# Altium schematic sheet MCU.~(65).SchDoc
size A3; SheetNumber: 10; SheetTotal: 12
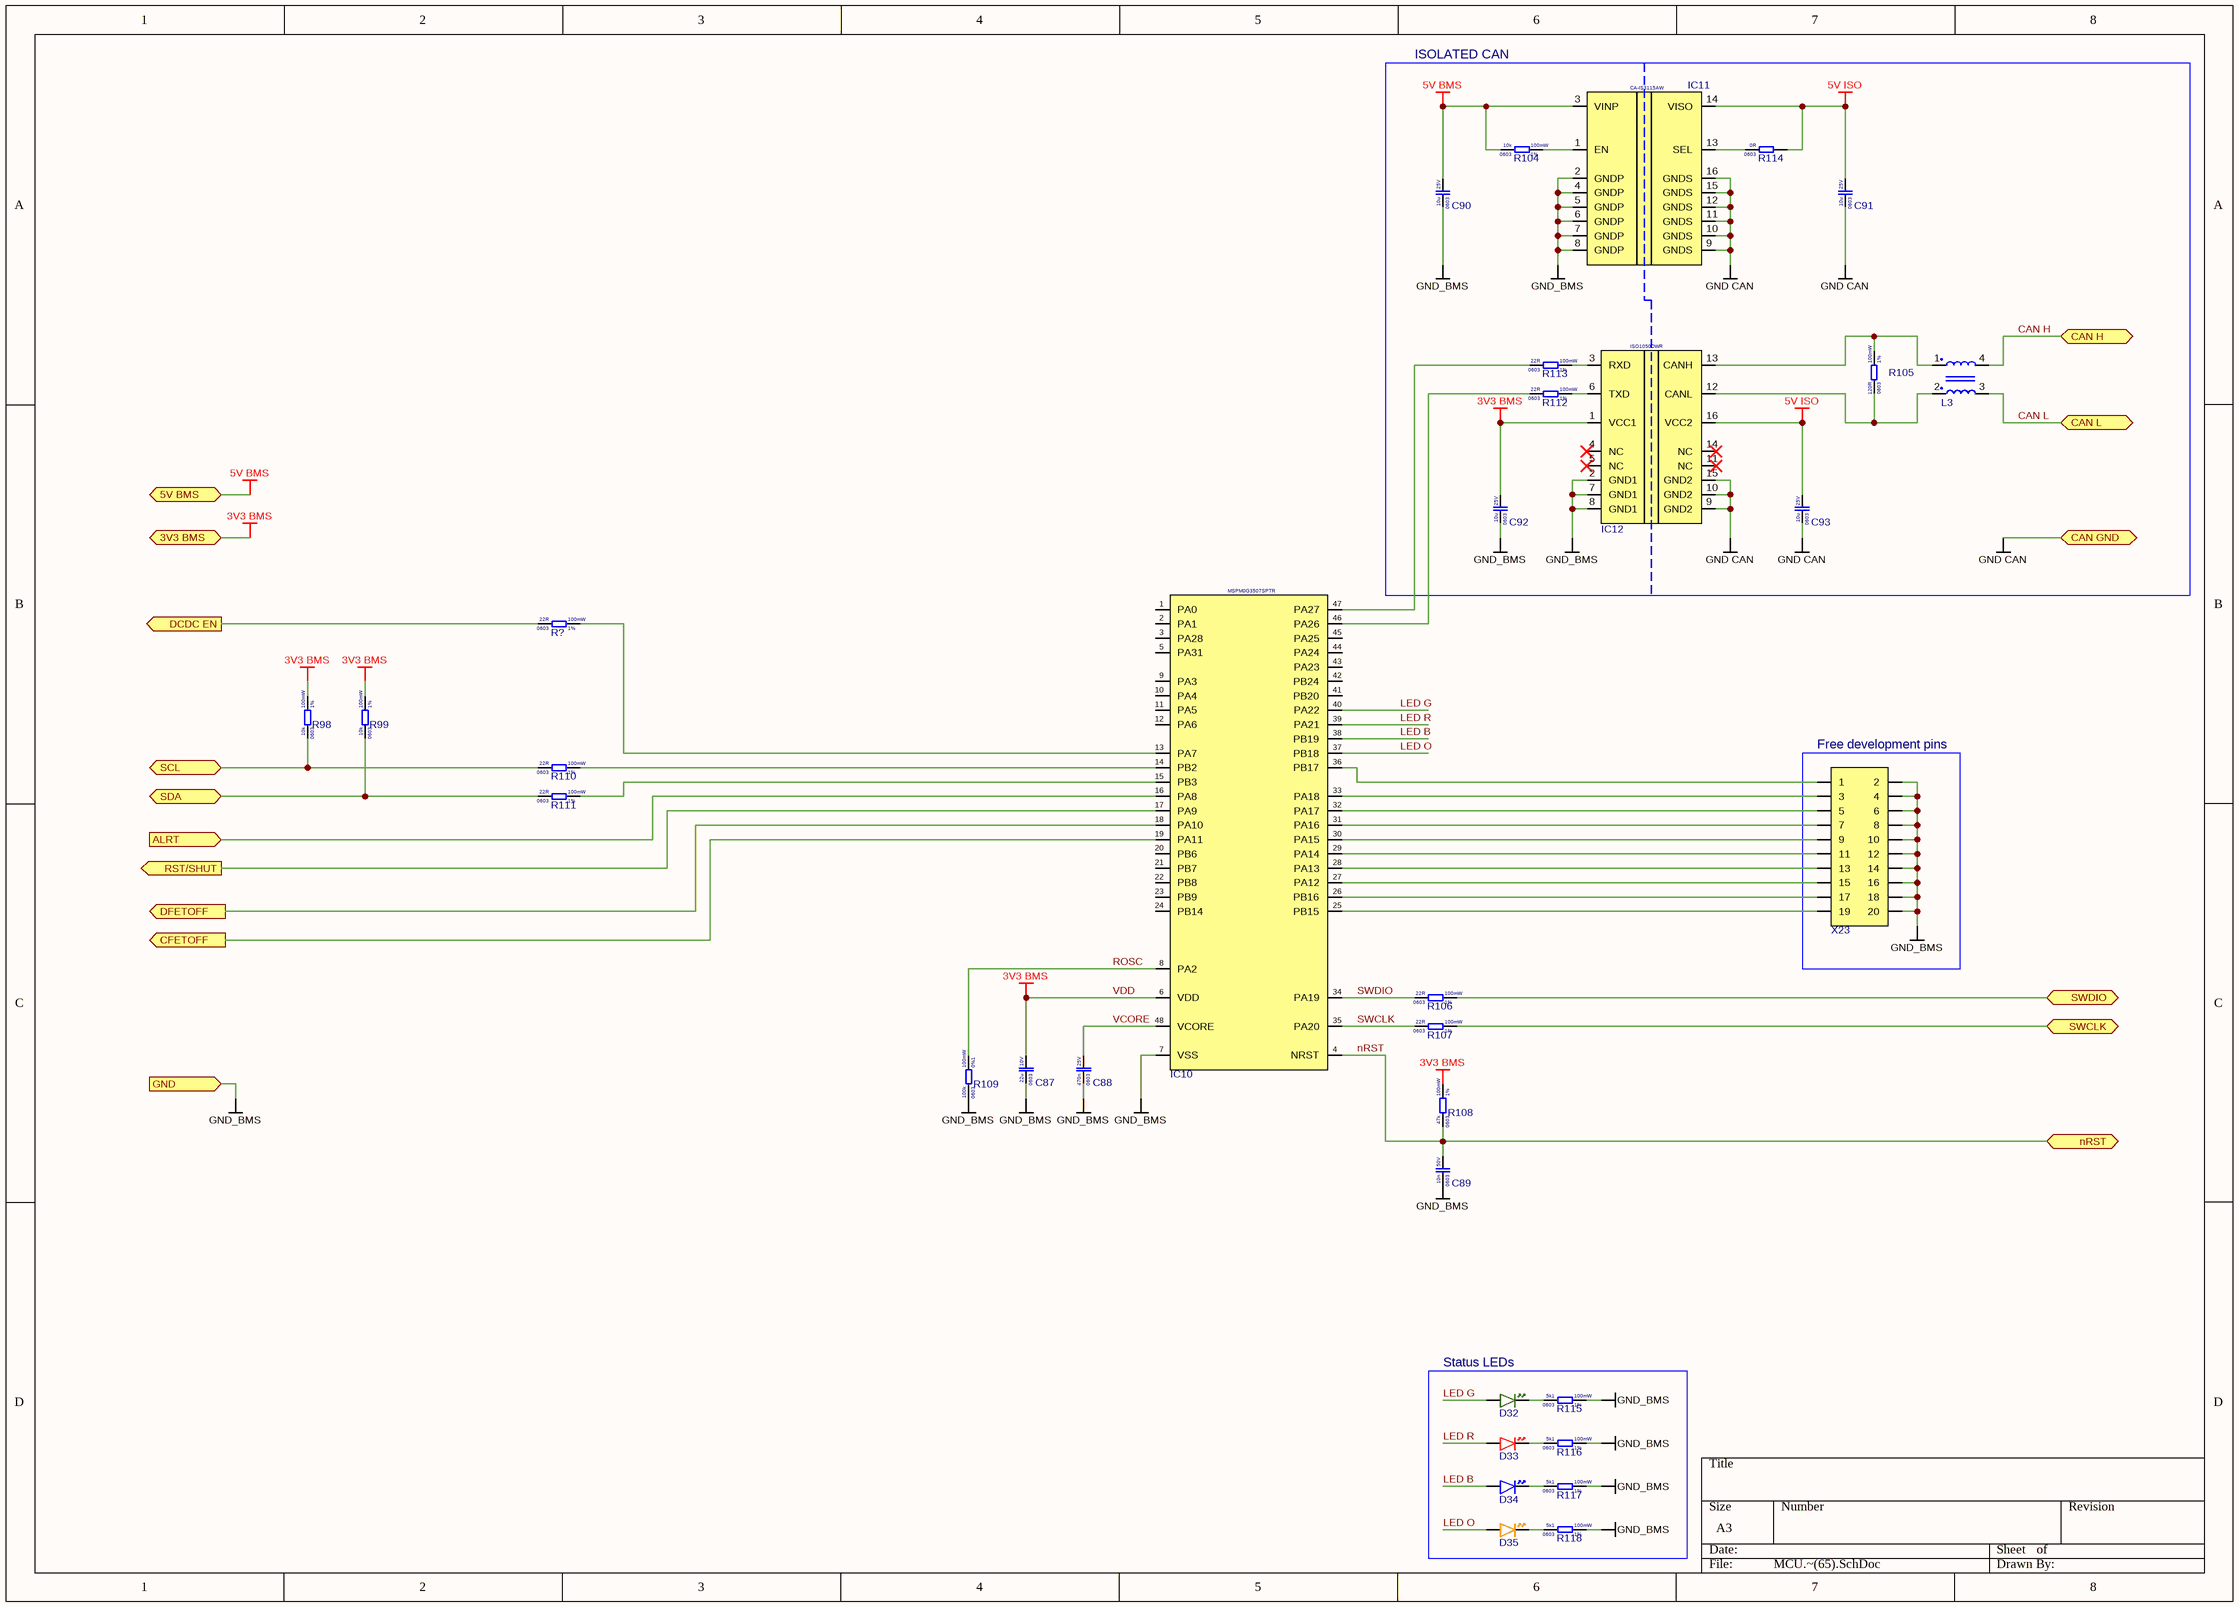
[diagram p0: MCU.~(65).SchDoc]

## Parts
C87  Voltage Rating: 10V  Case Code (Imperial): 0603  Capacitance: 22u  [CAP 0603]  (hidden comment: CGA0603X5R226M100JT)
C88  Voltage Rating: 25V  Case Code (Imperial): 0603  Capacitance: 470n  [CAP 0603]  (hidden comment: CL10B474KA8NNNC)
C89  Voltage Rating: 50V  Case Code (Imperial): 0603  Capacitance: 10n  [CAP 0603]  (hidden comment: 0603B103K500NT)
C90  Voltage Rating: 25V  Case Code (Imperial): 0603  Capacitance: 10u  [CAP 0603]  (hidden comment: CL10A106MA8NRNC)
C91  Voltage Rating: 25V  Case Code (Imperial): 0603  Capacitance: 10u  [CAP 0603]  (hidden comment: CL10A106MA8NRNC)
C92  Voltage Rating: 25V  Case Code (Imperial): 0603  Capacitance: 10u  [CAP 0603]  (hidden comment: CL10A106MA8NRNC)
C93  Voltage Rating: 25V  Case Code (Imperial): 0603  Capacitance: 10u  [CAP 0603]  (hidden comment: CL10A106MA8NRNC)
D32  PSC-1608U52GC-G4  [DIODE_0603_GREEN]  (value not drawn)
D33  XL-1608SURC-06  [DIODE_0603_RED]  (value not drawn)
D34  XL-1608UBC-04  [DIODE_0603]  (value not drawn)
D35  XL-1608UOC-06  [DIODE_0603_ORANGE]  (value not drawn)
IC10  MSPM0G3507SPTR  [LQFP-48]
IC11  CA-IS3115AW  [SOIC-16-WB]
IC12  ISO1050DWR  [SOIC-16-WB]
L3  ACM2012-900-2P-T002  [ACM2012-900-2P-T002]  (value not drawn)
R98  Resistance Tolerance: 1%  Resistance: 10k  Power Rating: 100mW  Case Code (Imperial): 0603  [RES_0603]  (hidden comment: 0603WAF1002T5E)
R99  Resistance Tolerance: 1%  Resistance: 10k  Power Rating: 100mW  Case Code (Imperial): 0603  [RES_0603]  (hidden comment: 0603WAF1002T5E)
R104  Resistance Tolerance: 1%  Resistance: 10k  Power Rating: 100mW  Case Code (Imperial): 0603  [RES_0603]  (hidden comment: 0603WAF1002T5E)
R105  Resistance Tolerance: 1%  Resistance: 120R  Power Rating: 100mW  Case Code (Imperial): 0603  [RES_0603]  (hidden comment: 0603WAF1200T5E)
R106  Resistance Tolerance: 1%  Resistance: 22R  Power Rating: 100mW  Case Code (Imperial): 0603  [RES_0603]  (hidden comment: 0603WAF220JT5E)
R107  Resistance Tolerance: 1%  Resistance: 22R  Power Rating: 100mW  Case Code (Imperial): 0603  [RES_0603]  (hidden comment: 0603WAF220JT5E)
R108  Resistance Tolerance: 1%  Resistance: 47k  Power Rating: 100mW  Case Code (Imperial): 0603  [RES_0603]  (hidden comment: 0603WAF4702T5E)
R109  Resistance Tolerance: 0%1  Resistance: 100k  Power Rating: 100mW  Case Code (Imperial): 0603  [RES_0603]  (hidden comment: RT0603BRD07100KL)
R110  Resistance Tolerance: 1%  Resistance: 22R  Power Rating: 100mW  Case Code (Imperial): 0603  [RES_0603]  (hidden comment: 0603WAF220JT5E)
R111  Resistance Tolerance: 1%  Resistance: 22R  Power Rating: 100mW  Case Code (Imperial): 0603  [RES_0603]  (hidden comment: 0603WAF220JT5E)
R112  Resistance Tolerance: 1%  Resistance: 22R  Power Rating: 100mW  Case Code (Imperial): 0603  [RES_0603]  (hidden comment: 0603WAF220JT5E)
R113  Resistance Tolerance: 1%  Resistance: 22R  Power Rating: 100mW  Case Code (Imperial): 0603  [RES_0603]  (hidden comment: 0603WAF220JT5E)
R114  Resistance: 0R  Case Code (Imperial): 0603  [RES_0603]  (hidden comment: 0603WAF0000T5E)
R115  Resistance Tolerance: 1%  Resistance: 5k1  Power Rating: 100mW  Case Code (Imperial): 0603  [RES_0603]  (hidden comment: 0603WAF5101T5E)
R116  Resistance Tolerance: 1%  Resistance: 5k1  Power Rating: 100mW  Case Code (Imperial): 0603  [RES_0603]  (hidden comment: 0603WAF5101T5E)
R117  Resistance Tolerance: 1%  Resistance: 5k1  Power Rating: 100mW  Case Code (Imperial): 0603  [RES_0603]  (hidden comment: 0603WAF5101T5E)
R118  Resistance Tolerance: 1%  Resistance: 5k1  Power Rating: 100mW  Case Code (Imperial): 0603  [RES_0603]  (hidden comment: 0603WAF5101T5E)
R?  Resistance Tolerance: 1%  Resistance: 22R  Power Rating: 100mW  Case Code (Imperial): 0603  [RES_0603]  (hidden comment: 0603WAF220JT5E)
X23  PZ254V-12-20P  [Pin header 2x10 2.54mm THT Vertical]  (value not drawn)

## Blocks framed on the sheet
ISOLATED CAN: C90-C93 IC11 IC12 L3 R104 R105 R112-R114
Free development pins: X23
Status LEDs: D32-D35 R115-R118

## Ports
3V3 BMS (bidir, see BMS[4B]), 5V BMS (bidir, see BMS[4B], BAT+ to 5V STEP-DOWN[7B]), ALRT (in, see BMS[4B], BQ76952 BMS[7C]), CAN GND (bidir, see BMS[4B], BMS[8B]), CAN H (bidir, see BMS[4B], BMS[8B], ESD system side[2B]), CAN L (bidir, see BMS[4B], BMS[8B], ESD system side[2B]), CFETOFF (out, see BMS[4B], BQ76952 BMS[7C]), DCDC EN (out, see BMS[4B]), DFETOFF (out, see BMS[4B], BQ76952 BMS[7C]), GND (in, see BMS[4C], BAT+ to 5V STEP-DOWN[3C], BQ76952 BMS[1D]), nRST (bidir, see BMS[4B], BMS[8B]), RST/SHUT (out, see BMS[4B], BQ76952 BMS[7C]), SCL (bidir, see BMS[4C], BMS[8C], BQ76952 BMS[7C]), SDA (bidir, see BMS[4C], BMS[8C], BQ76952 BMS[7C]), SWCLK (bidir, see BMS[4B], BMS[8B]), SWDIO (bidir, see BMS[4B], BMS[8B])

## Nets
5V BMS: C90.2 IC11.3(VINP) R104.1 ; port 5V BMS
5V ISO: C91.2 C93.2 IC11.14(VISO) IC12.16(VCC2) R114.2
GND CAN: C91.1 C93.1 IC11.9(GNDS) IC11.10(GNDS) IC11.11(GNDS) IC11.12(GNDS) IC11.15(GNDS) IC11.16(GNDS) IC12.9(GND2) IC12.10(GND2) IC12.15(GND2) ; port CAN GND
GND_BMS: C87.1 C88.1 C89.1 C90.1 C92.1 IC10.7(VSS) IC11.2(GNDP) IC11.4(GNDP) IC11.5(GNDP) IC11.6(GNDP) IC11.7(GNDP) IC11.8(GNDP) IC12.2(GND1) IC12.7(GND1) IC12.8(GND1) R109.1 R115.2 R116.2 R117.2 R118.2 X23.2 X23.4 X23.6 X23.8 X23.10 X23.12 X23.14 X23.16 X23.18 X23.20 ; port GND
VDD: C87.2 C92.2 IC10.6(VDD) IC12.1(VCC1) R98.2 R99.2 R108.2 ; port 3V3 BMS  [also labelled 3V3 BMS]
ALRT: IC10.16(PA8) ; port ALRT
CAN H: L3.4 ; port CAN H
CAN L: L3.3 ; port CAN L
CFETOFF: IC10.19(PA11) ; port CFETOFF
DCDC EN: R?.1 ; port DCDC EN
DFETOFF: IC10.18(PA10) ; port DFETOFF
LED B: D34.A IC10.38(PB19)
LED G: D32.A IC10.40(PA22)
LED O: D35.A IC10.37(PB18)
LED R: D33.A IC10.39(PA21)
nRST: C89.2 IC10.4(NRST) R108.1 ; port nRST
ROSC: IC10.8(PA2) R109.2
RST/SHUT: IC10.17(PA9) ; port RST/SHUT
SCL: R98.1 R110.1 ; port SCL
SDA: R99.1 R111.1 ; port SDA
SWCLK: IC10.35(PA20) R107.1
SWCLK: R107.2 ; port SWCLK  [a separate net that carries the same name]
SWDIO: IC10.34(PA19) R106.1
SWDIO: R106.2 ; port SWDIO  [a separate net that carries the same name]
VCORE: C88.2 IC10.48(VCORE)
NetD32_K: D32.K R115.1
NetD33_K: D33.K R116.1
NetD34_K: D34.K R117.1
NetD35_K: D35.K R118.1
NetIC10_13: IC10.13(PA7) R?.2
NetIC10_14: IC10.14(PB2) R110.2
NetIC10_15: IC10.15(PB3) R111.2
NetIC10_25: IC10.25(PB15) X23.19
NetIC10_26: IC10.26(PB16) X23.17
NetIC10_27: IC10.27(PA12) X23.15
NetIC10_28: IC10.28(PA13) X23.13
NetIC10_29: IC10.29(PA14) X23.11
NetIC10_30: IC10.30(PA15) X23.9
NetIC10_31: IC10.31(PA16) X23.7
NetIC10_32: IC10.32(PA17) X23.5
NetIC10_33: IC10.33(PA18) X23.3
NetIC10_36: IC10.36(PB17) X23.1
NetIC10_46: IC10.46(PA26) R112.1
NetIC10_47: IC10.47(PA27) R113.1
NetIC11_1: IC11.1(EN) R104.2
NetIC11_13: IC11.13(SEL) R114.1
NetIC12_3: IC12.3(RXD) R113.2
NetIC12_6: IC12.6(TXD) R112.2
NetIC12_12: IC12.12(CANL) L3.2 R105.1
NetIC12_13: IC12.13(CANH) L3.1 R105.2

Not connected (* = marked no-connect by the designer): IC10 1(PA0) 2(PA1) 3(PA28) 5(PA31) 9(PA3) 10(PA4) 11(PA5) 12(PA6) 20(PB6) 21(PB7) 22(PB8) 23(PB9) 24(PB14) 41(PB20) 42(PB24) 43(PA23) 44(PA24) 45(PA25); IC12 4(NC)* 5(NC)* 11(NC)* 14(NC)*

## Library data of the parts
C87 = CGA0603X5R226M100JT: Cap 22uF 10V 0603 X5R; Manufacturer: HRE
C88 = CL10B474KA8NNNC: Cap 470nF 25V 0603 X7R; Manufacturer: Samsung
C89 = 0603B103K500NT: Cap 10nF 50V 0603 X7R; Manufacturer: FH
C90-C93 = CL10A106MA8NRNC: Cap 10uF 25V 0603 X5R; Manufacturer: Samsung
D32 = PSC-1608U52GC-G4: LED Green 0603 20mA; Manufacturer: HONGLITRONIC
D33 = XL-1608SURC-06: LED Red 0603 25mA; Manufacturer: Xinglight
D34 = XL-1608UBC-04: LED Blue 0603 25mA; Manufacturer: Xinglight
D35 = XL-1608UOC-06: LED Orange 0603 20mA; Manufacturer: XINGLIGHT
IC10 = MSPM0G3507SPTR: MCU MSPM0G3507SPTR LQFP-48; Manufacturer: Texas Instruments
IC11 = CA-IS3115AW: DCDC Module Isolated 5Vin 5Vout 1.5W SOIC-16-WB; Manufacturer: Chipanalog
IC12 = ISO1050DWR: CAN ISO transciever SOIC-16-WB; Manufacturer: Texas Instruments
L3 = ACM2012-900-2P-T002: CMC 90R@100MHz 190mR 400mA 50V; Manufacturer: TDK
R98 R99 R104 = 0603WAF1002T5E: Res 10k 0603 1% 100mW 75V; Manufacturer: Uni-Royal
R105 = 0603WAF1200T5E: Res 120R 0603 1% 100mW 75V; Manufacturer: Uni-Royal; Manufacturer Part Number: 0603WAF5101T5E
R106 R107 R110-R113 R? = 0603WAF220JT5E: Res 22R 0603 1% 100mW 75V; Manufacturer: Uni-Royal
R108 = 0603WAF4702T5E: Res 47k 0603 1% 100mW 75V; Manufacturer: Uni-Royal
R109 = RT0603BRD07100KL: Res 100k 0603 0.1% 100mW 75V 25ppm; Manufacturer: YAGEO
R114 = 0603WAF0000T5E: Res 0R 0603 1% 100mW 75V; Manufacturer: UNI-ROYAL
R115-R118 = 0603WAF5101T5E: Res 5k1 0603 1% 100mW 75V; Manufacturer: Uni-Royal
X23 = PZ254V-12-20P: Pin header 2x10 2.54mm THT Vertical; Manufacturer: XFCN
